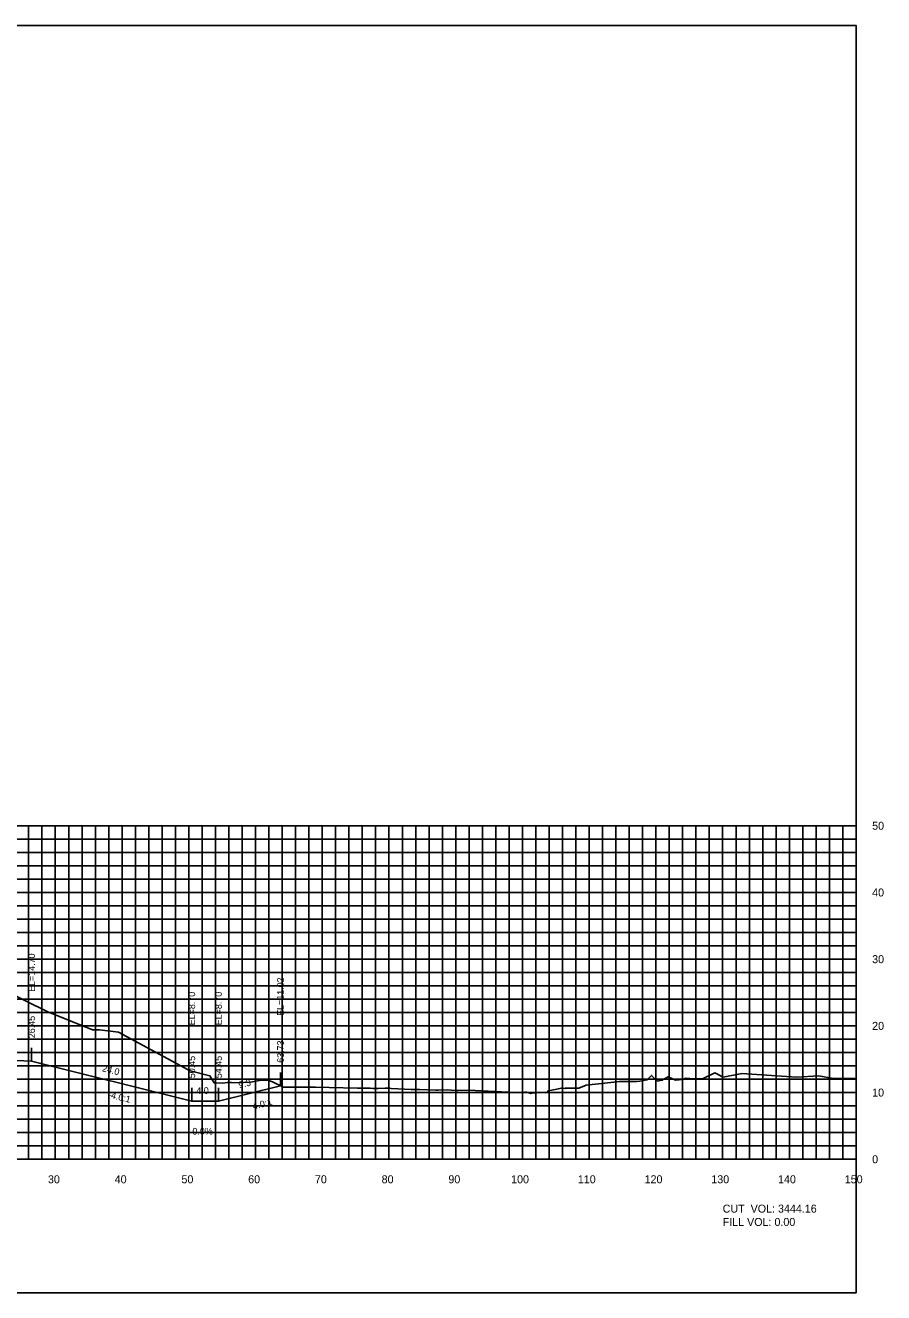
# Model space of a CAD drawing. Extents: x 1800976 to 1805104, y 250057 to 250580.
# Drawn here: x 1804016.5 to 1804145.1, y 250079.4 to 250269.4 of the extents above; entities that cross this region are included whole.
import ezdxf

# ---------------------------------------------------------------- set-up
doc = ezdxf.new("R2010")
doc.units = 0
for name, color, linetype in [('10', 7, 'Continuous'), ('3', 7, 'Continuous'), ('31', 7, 'Continuous'), ('4', 7, 'Continuous'), ('60', 7, 'Continuous'), ('ANNO-TXT', 7, 'Continuous'), ('CL-CNST', 7, 'Continuous'), ('Level 62', 7, 'Continuous'), ('M-ROADS', 7, 'Continuous')]:
    doc.layers.add(name, color=color, linetype=linetype)

msp = doc.modelspace()

# ---------------------------------------------------------------- linework, layer by layer
for p, q in [((1804017.45, 250114.13), (1804017.45, 250116.13)), ((1804054.74, 250110.45), (1804054.74, 250112.45)), ((1804041.45, 250108.13), (1804041.45, 250110.13)), ((1804045.45, 250108.13), (1804045.45, 250110.13))]:
    msp.add_line(p, q)
msp.add_lwpolyline([(1803841, 250079.43), (1804141, 250079.43), (1804141, 250269.43), (1803841, 250269.43)], close=True)
at = {"layer": '60'}
for p, q in [((1804141, 250099.43), (1804141, 250149.43)), ((1804141.06, 250149.43), (1804141, 250149.43)), ((1804141.06, 250139.43), (1804141, 250139.43)), ((1804141.06, 250129.43), (1804141, 250129.43)), ((1804141.06, 250119.43), (1804141, 250119.43)), ((1804141.06, 250109.43), (1804141, 250109.43)), ((1803841, 250099.43), (1804141, 250099.43)), ((1804021, 250099.37), (1804021, 250099.43)), ((1804031, 250099.37), (1804031, 250099.43)), ((1804041, 250099.37), (1804041, 250099.43)), ((1804051, 250099.37), (1804051, 250099.43)), ((1804061, 250099.37), (1804061, 250099.43)), ((1804071, 250099.37), (1804071, 250099.43)), ((1804081, 250099.37), (1804081, 250099.43)), ((1804091, 250099.37), (1804091, 250099.43)), ((1804101, 250099.37), (1804101, 250099.43)), ((1804111, 250099.37), (1804111, 250099.43)), ((1804121, 250099.37), (1804121, 250099.43)), ((1804131, 250099.37), (1804131, 250099.43)), ((1804141, 250099.37), (1804141, 250099.43)), ((1804141.06, 250099.43), (1804141, 250099.43))]:
    msp.add_line(p, q, dxfattribs=at)
at = {"layer": 'CL-CNST'}
msp.add_lwpolyline([(1803947.75, 250115.92), (1803955, 250115.76), (1803991, 250114.96), (1804003.59, 250114.69), (1804011.59, 250114.37), (1804017.45, 250114.13), (1804041.45, 250108.13), (1804045.45, 250108.13), (1804054.74, 250110.45)], dxfattribs=at)
at = {"layer": 'Level 62'}
for p, q in [((1803841, 250149.43), (1804141, 250149.43)), ((1804017, 250099.43), (1804017, 250149.43)), ((1804019, 250099.43), (1804019, 250149.43)), ((1804021, 250099.43), (1804021, 250149.43)), ((1804023, 250099.43), (1804023, 250149.43)), ((1804025, 250099.43), (1804025, 250149.43)), ((1804027, 250099.43), (1804027, 250149.43)), ((1804029, 250099.43), (1804029, 250149.43)), ((1804031, 250099.43), (1804031, 250149.43)), ((1804033, 250099.43), (1804033, 250149.43)), ((1804035, 250099.43), (1804035, 250149.43)), ((1804037, 250099.43), (1804037, 250149.43)), ((1804039, 250099.43), (1804039, 250149.43)), ((1804041, 250099.43), (1804041, 250149.43)), ((1804043, 250099.43), (1804043, 250149.43)), ((1804045, 250099.43), (1804045, 250149.43)), ((1804047, 250099.43), (1804047, 250149.43)), ((1804049, 250099.43), (1804049, 250149.43)), ((1804051, 250099.43), (1804051, 250149.43)), ((1804053, 250099.43), (1804053, 250149.43)), ((1804055, 250099.43), (1804055, 250149.43)), ((1804057, 250099.43), (1804057, 250149.43)), ((1804059, 250099.43), (1804059, 250149.43)), ((1804061, 250099.43), (1804061, 250149.43)), ((1804063, 250099.43), (1804063, 250149.43)), ((1804065, 250099.43), (1804065, 250149.43)), ((1804067, 250099.43), (1804067, 250149.43)), ((1804069, 250099.43), (1804069, 250149.43)), ((1804071, 250099.43), (1804071, 250149.43)), ((1804073, 250099.43), (1804073, 250149.43)), ((1804075, 250099.43), (1804075, 250149.43)), ((1804077, 250099.43), (1804077, 250149.43)), ((1804079, 250099.43), (1804079, 250149.43)), ((1804081, 250099.43), (1804081, 250149.43)), ((1804083, 250099.43), (1804083, 250149.43)), ((1804085, 250099.43), (1804085, 250149.43)), ((1804087, 250099.43), (1804087, 250149.43)), ((1804089, 250099.43), (1804089, 250149.43)), ((1804091, 250099.43), (1804091, 250149.43)), ((1804093, 250099.43), (1804093, 250149.43)), ((1804095, 250099.43), (1804095, 250149.43)), ((1804097, 250099.43), (1804097, 250149.43)), ((1804099, 250099.43), (1804099, 250149.43)), ((1804101, 250099.43), (1804101, 250149.43)), ((1804103, 250099.43), (1804103, 250149.43)), ((1804105, 250099.43), (1804105, 250149.43)), ((1804107, 250099.43), (1804107, 250149.43)), ((1804109, 250099.43), (1804109, 250149.43)), ((1804111, 250099.43), (1804111, 250149.43)), ((1804113, 250099.43), (1804113, 250149.43)), ((1804115, 250099.43), (1804115, 250149.43)), ((1804117, 250099.43), (1804117, 250149.43)), ((1804119, 250099.43), (1804119, 250149.43)), ((1804121, 250099.43), (1804121, 250149.43)), ((1804123, 250099.43), (1804123, 250149.43)), ((1804125, 250099.43), (1804125, 250149.43)), ((1804127, 250099.43), (1804127, 250149.43)), ((1804129, 250099.43), (1804129, 250149.43)), ((1804131, 250099.43), (1804131, 250149.43)), ((1804133, 250099.43), (1804133, 250149.43)), ((1804135, 250099.43), (1804135, 250149.43)), ((1804137, 250099.43), (1804137, 250149.43)), ((1804139, 250099.43), (1804139, 250149.43)), ((1804141, 250099.43), (1804141, 250149.43)), ((1803841, 250147.43), (1804141, 250147.43)), ((1803841, 250145.43), (1804141, 250145.43)), ((1803841, 250143.43), (1804141, 250143.43)), ((1803841, 250141.43), (1804141, 250141.43)), ((1803841, 250139.43), (1804141, 250139.43)), ((1803841, 250137.43), (1804141, 250137.43)), ((1803841, 250135.43), (1804141, 250135.43)), ((1803841, 250133.43), (1804141, 250133.43)), ((1803841, 250131.43), (1804141, 250131.43)), ((1803841, 250129.43), (1804141, 250129.43)), ((1803841, 250127.43), (1804141, 250127.43)), ((1803841, 250125.43), (1804141, 250125.43)), ((1803841, 250123.43), (1804141, 250123.43)), ((1803841, 250121.43), (1804141, 250121.43)), ((1803841, 250119.43), (1804141, 250119.43)), ((1803841, 250117.43), (1804141, 250117.43)), ((1803841, 250115.43), (1804141, 250115.43)), ((1803841, 250113.43), (1804141, 250113.43)), ((1803841, 250111.43), (1804141, 250111.43)), ((1803841, 250109.43), (1804141, 250109.43)), ((1803841, 250107.43), (1804141, 250107.43)), ((1803841, 250105.43), (1804141, 250105.43)), ((1803841, 250103.43), (1804141, 250103.43)), ((1803841, 250101.43), (1804141, 250101.43)), ((1803841, 250099.43), (1804141, 250099.43))]:
    msp.add_line(p, q, dxfattribs=at)
at = {"layer": 'M-ROADS'}
msp.add_lwpolyline([(1804012.9, 250124.98), (1804019.87, 250121.52), (1804026.57, 250118.82), (1804026.98, 250118.82), (1804027.63, 250118.82), (1804030.49, 250118.47), (1804040.92, 250112.82), (1804041.19, 250112.67), (1804044.17, 250111.94), (1804044.78, 250110.89), (1804046.11, 250110.85), (1804046.77, 250110.93), (1804047.4, 250110.92), (1804048.65, 250110.9), (1804049.75, 250110.97), (1804049.98, 250110.96), (1804051.83, 250111.3), (1804052.07, 250111.31), (1804052.17, 250111.31), (1804052.95, 250111.25), (1804053.52, 250111.03), (1804055.17, 250110.25), (1804055.8, 250110.25), (1804056.88, 250110.26), (1804057.5, 250110.26), (1804057.8, 250110.25), (1804058.27, 250110.23), (1804058.81, 250110.24), (1804059.98, 250110.25), (1804062.04, 250110.2), (1804066.28, 250110.07), (1804067.18, 250110.08), (1804067.98, 250110.09), (1804068.19, 250110.08), (1804068.58, 250110.06), (1804069.11, 250110.05), (1804069.39, 250110.03), (1804070.45, 250110.07), (1804071.09, 250110.09), (1804071.31, 250110.04), (1804074.33, 250109.87), (1804075.08, 250109.87), (1804075.55, 250109.87), (1804078.01, 250109.78), (1804078.08, 250109.77), (1804078.39, 250109.78), (1804079.79, 250109.82), (1804080.32, 250109.78), (1804081.07, 250109.76), (1804081.19, 250109.76), (1804081.33, 250109.76), (1804082.9, 250109.79), (1804085.85, 250109.65), (1804089.91, 250109.46), (1804091.33, 250109.49), (1804091.56, 250109.5), (1804091.62, 250109.5), (1804092.28, 250109.3), (1804092.46, 250109.32), (1804093.17, 250109.37), (1804094.31, 250109.46), (1804094.69, 250109.42), (1804094.83, 250109.68), (1804095.64, 250109.85), (1804096.83, 250110.1), (1804097.36, 250110.06), (1804097.45, 250110.1), (1804099.43, 250110.1), (1804100.54, 250110.56), (1804105.14, 250111.05), (1804105.55, 250111.07), (1804105.75, 250111.08), (1804106.49, 250111.08), (1804108.14, 250111.08), (1804108.59, 250111.15), (1804109.71, 250111.32), (1804110.32, 250112), (1804110.34, 250111.99), (1804111.24, 250111.15), (1804111.85, 250111.27), (1804111.99, 250111.29), (1804112.07, 250111.38), (1804112.84, 250111.81), (1804113.94, 250111.31), (1804115.06, 250111.4), (1804115.41, 250111.6), (1804116.79, 250111.48), (1804117.97, 250111.48), (1804119.71, 250112.34), (1804119.82, 250112.38), (1804121.08, 250111.75), (1804123.88, 250112.29), (1804132.06, 250111.72), (1804135.4, 250111.96), (1804137.55, 250111.55), (1804137.61, 250111.55), (1804137.66, 250111.57), (1804138.04, 250111.52), (1804139.72, 250111.54), (1804140.7, 250111.54), (1804141, 250111.54)], dxfattribs=at)

# ---------------------------------------------------------------- texts
for s, rotation, p in [('-4.0:1', 345.9638, (1804028.84, 250108.71)), ('4.0:1', 14.0362, (1804050.7, 250106.87))]:
    msp.add_text(s, height=1, rotation=rotation).set_placement(p)
at = {"layer": '10'}
for s, p in [('30', (1804019.9, 250095.83)), ('40', (1804029.9, 250095.83)), ('50', (1804039.9, 250095.83)), ('60', (1804049.9, 250095.83)), ('70', (1804059.9, 250095.83)), ('80', (1804069.9, 250095.83)), ('90', (1804079.9, 250095.83)), ('100', (1804089.3, 250095.83)), ('110', (1804099.3, 250095.83)), ('120', (1804109.3, 250095.83)), ('130', (1804119.3, 250095.83)), ('140', (1804129.3, 250095.83)), ('150', (1804139.3, 250095.83))]:
    msp.add_text(s, height=1.2, dxfattribs=at).set_placement(p)
at = {"layer": '3'}
for s, p in [('EL=14.70', (1804017.95, 250124.53)), ('EL=11.02', (1804055.24, 250120.93)), ('EL=8.70', (1804041.95, 250119.52)), ('EL=8.70', (1804045.95, 250119.52)), ('26.45', (1804017.95, 250117.58)), ('63.73', (1804055.24, 250113.9)), ('50.45', (1804041.95, 250111.58)), ('54.45', (1804045.95, 250111.58))]:
    msp.add_text(s, height=1, rotation=90, dxfattribs=at).set_placement(p)
at = {"layer": '31'}
for s, p in [('50', (1804143.4, 250148.83)), ('40', (1804143.4, 250138.83)), ('30', (1804143.4, 250128.83)), ('20', (1804143.4, 250118.83)), ('10', (1804143.4, 250108.83)), ('0', (1804143.4, 250098.83))]:
    msp.add_text(s, height=1.2, dxfattribs=at).set_placement(p)
at = {"layer": '4'}
for s, rotation, p in [('24.0', 345.9638, (1804027.95, 250112.64)), ('9.3', 14.0362, (1804048.58, 250110.05))]:
    msp.add_text(s, height=1, rotation=rotation, dxfattribs=at).set_placement(p)
for s, p in [('4.0', (1804042.13, 250109.23)), ('0.0%', (1804041.54, 250103.13))]:
    msp.add_text(s, height=1, dxfattribs=at).set_placement(p)
at = {"layer": 'ANNO-TXT'}
for s, p in [('CUT  VOL: 3444.16', (1804121, 250091.43)), ('FILL VOL: 0.00', (1804121, 250089.43))]:
    msp.add_text(s, height=1.2, dxfattribs=at).set_placement(p)

doc.saveas('drawing.dxf')
